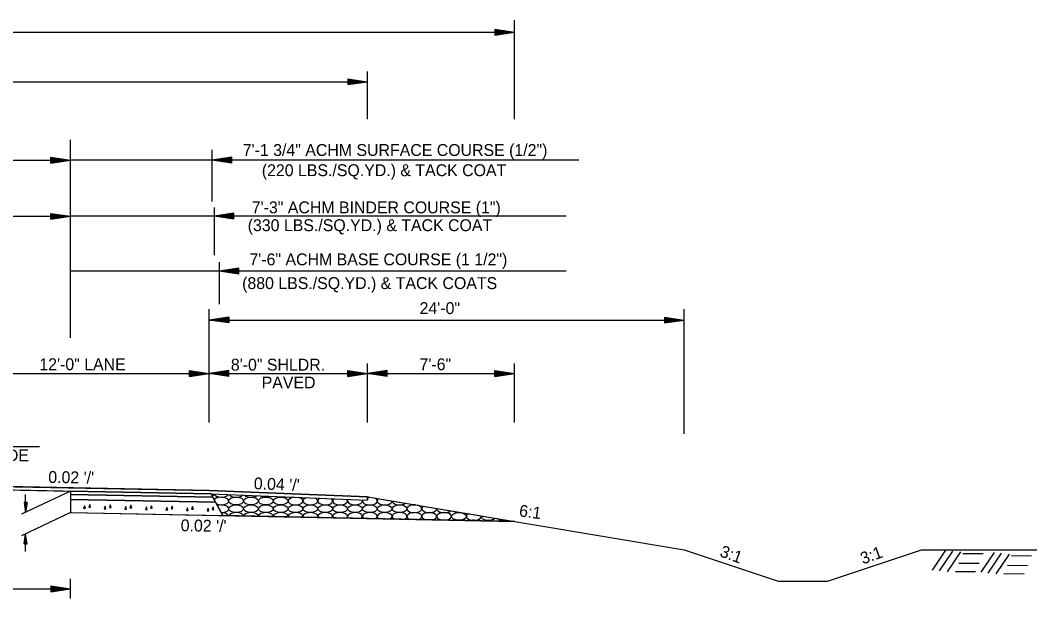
# Model space of a CAD drawing. Extents: x 1371763 to 1372860, y 385599 to 385872.
# Drawn here: x 1372091.9 to 1372143.2, y 385773 to 385802.2 of the extents above; entities that cross this region are included whole.
import ezdxf

# ---------------------------------------------------------------- set-up
doc = ezdxf.new("R2010")
doc.units = 0
doc.layers.add('R_Draft', color=7, linetype='Continuous')
doc.layers.add('R_Fin Surface', color=7, linetype='Continuous')

msp = doc.modelspace()

# ---------------------------------------------------------------- linework, layer by layer
at = {"layer": 'R_Draft'}
for p, q in [((1372115.827, 385801.752), (1372116.827, 385801.602)), ((1372115.827, 385801.752), (1372115.827, 385801.452)), ((1372116.827, 385797.204), (1372116.827, 385802.202)), ((1372049.964, 385801.602), (1372116.827, 385801.602)), ((1372115.827, 385801.727), (1372116.66, 385801.602)), ((1372115.827, 385801.701), (1372116.488, 385801.602)), ((1372115.827, 385801.676), (1372116.322, 385801.602)), ((1372115.827, 385801.65), (1372116.152, 385801.602)), ((1372115.827, 385801.625), (1372115.985, 385801.602)), ((1372115.827, 385801.452), (1372116.827, 385801.602)), ((1372115.827, 385801.553), (1372116.152, 385801.602)), ((1372115.827, 385801.502), (1372116.488, 385801.602)), ((1372115.827, 385801.477), (1372116.66, 385801.602)), ((1372115.827, 385801.527), (1372116.322, 385801.602)), ((1372115.827, 385801.578), (1372115.985, 385801.602)), ((1372108.395, 385799.252), (1372109.395, 385799.102)), ((1372108.395, 385799.252), (1372108.395, 385798.952)), ((1372108.395, 385799.227), (1372109.228, 385799.102)), ((1372108.395, 385799.201), (1372109.056, 385799.102)), ((1372109.395, 385797.204), (1372109.395, 385799.612)), ((1372057.395, 385799.102), (1372109.395, 385799.102)), ((1372108.395, 385799.176), (1372108.89, 385799.102)), ((1372108.395, 385799.15), (1372108.72, 385799.102)), ((1372108.395, 385799.125), (1372108.553, 385799.102)), ((1372108.395, 385798.952), (1372109.395, 385799.102)), ((1372108.395, 385799.053), (1372108.72, 385799.102)), ((1372108.395, 385799.002), (1372109.056, 385799.102)), ((1372108.395, 385798.977), (1372109.228, 385799.102)), ((1372108.395, 385799.027), (1372108.89, 385799.102)), ((1372108.395, 385799.078), (1372108.553, 385799.102)), ((1372094.394, 385786.159), (1372094.395, 385796.171)), ((1372101.532, 385795.66), (1372101.532, 385793.052)), ((1372072.395, 385795.139), (1372094.395, 385795.14)), ((1372093.395, 385795.29), (1372094.395, 385795.14)), ((1372093.395, 385794.99), (1372093.395, 385795.29)), ((1372093.395, 385795.265), (1372094.228, 385795.14)), ((1372093.395, 385795.239), (1372094.056, 385795.14)), ((1372093.395, 385795.214), (1372093.89, 385795.14)), ((1372093.395, 385795.189), (1372093.72, 385795.14)), ((1372093.395, 385795.163), (1372093.553, 385795.14)), ((1372093.395, 385794.99), (1372094.395, 385795.14)), ((1372093.395, 385795.091), (1372093.72, 385795.14)), ((1372093.395, 385795.04), (1372094.056, 385795.14)), ((1372093.395, 385795.015), (1372094.228, 385795.14)), ((1372093.395, 385795.065), (1372093.89, 385795.14)), ((1372093.395, 385795.116), (1372093.553, 385795.14)), ((1372120.071, 385795.139), (1372094.395, 385795.14)), ((1372102.532, 385795.29), (1372101.532, 385795.14)), ((1372102.532, 385794.99), (1372101.532, 385795.14)), ((1372102.532, 385795.265), (1372101.699, 385795.14)), ((1372102.532, 385795.015), (1372101.699, 385795.14)), ((1372102.532, 385795.239), (1372101.871, 385795.14)), ((1372102.532, 385795.04), (1372101.871, 385795.14)), ((1372102.532, 385795.214), (1372102.037, 385795.14)), ((1372102.532, 385795.065), (1372102.037, 385795.14)), ((1372102.532, 385795.189), (1372102.207, 385795.14)), ((1372102.532, 385795.091), (1372102.207, 385795.14)), ((1372102.532, 385795.163), (1372102.374, 385795.14)), ((1372102.532, 385795.116), (1372102.374, 385795.14)), ((1372102.532, 385794.99), (1372102.532, 385795.29)), ((1372101.647, 385792.752), (1372101.647, 385790.338)), ((1372072.395, 385792.301), (1372094.395, 385792.301)), ((1372093.395, 385792.451), (1372094.395, 385792.301)), ((1372093.395, 385792.151), (1372093.395, 385792.451)), ((1372093.395, 385792.426), (1372094.228, 385792.301)), ((1372093.395, 385792.401), (1372094.056, 385792.301)), ((1372093.395, 385792.376), (1372093.89, 385792.301)), ((1372093.395, 385792.35), (1372093.72, 385792.301)), ((1372093.395, 385792.325), (1372093.553, 385792.301)), ((1372093.395, 385792.151), (1372094.395, 385792.301)), ((1372093.395, 385792.253), (1372093.72, 385792.301)), ((1372093.395, 385792.202), (1372094.056, 385792.301)), ((1372093.395, 385792.176), (1372094.228, 385792.301)), ((1372093.395, 385792.227), (1372093.89, 385792.301)), ((1372093.395, 385792.278), (1372093.553, 385792.301)), ((1372119.437, 385792.302), (1372094.395, 385792.302)), ((1372102.647, 385792.452), (1372101.647, 385792.302)), ((1372102.647, 385792.152), (1372101.647, 385792.302)), ((1372102.647, 385792.427), (1372101.814, 385792.302)), ((1372102.647, 385792.177), (1372101.814, 385792.302)), ((1372102.647, 385792.401), (1372101.986, 385792.302)), ((1372102.647, 385792.202), (1372101.986, 385792.302)), ((1372102.647, 385792.376), (1372102.152, 385792.302)), ((1372102.647, 385792.227), (1372102.152, 385792.302)), ((1372102.647, 385792.351), (1372102.322, 385792.302)), ((1372102.647, 385792.253), (1372102.322, 385792.302)), ((1372102.647, 385792.325), (1372102.489, 385792.302)), ((1372102.647, 385792.278), (1372102.489, 385792.302)), ((1372102.647, 385792.152), (1372102.647, 385792.452)), ((1372101.896, 385789.977), (1372101.896, 385787.861)), ((1372119.437, 385789.527), (1372094.395, 385789.527)), ((1372102.896, 385789.677), (1372101.896, 385789.527)), ((1372102.896, 385789.377), (1372101.896, 385789.527)), ((1372102.896, 385789.652), (1372102.063, 385789.527)), ((1372102.896, 385789.402), (1372102.063, 385789.527)), ((1372102.896, 385789.626), (1372102.235, 385789.527)), ((1372102.896, 385789.427), (1372102.235, 385789.527)), ((1372102.896, 385789.601), (1372102.401, 385789.527)), ((1372102.896, 385789.452), (1372102.401, 385789.527)), ((1372102.896, 385789.576), (1372102.571, 385789.527)), ((1372102.896, 385789.478), (1372102.571, 385789.527)), ((1372102.896, 385789.55), (1372102.738, 385789.527)), ((1372102.896, 385789.503), (1372102.738, 385789.527)), ((1372102.896, 385789.377), (1372102.896, 385789.677)), ((1372101.392, 385781.89), (1372101.393, 385787.604)), ((1372125.393, 385781.306), (1372125.393, 385787.604)), ((1372102.393, 385787.213), (1372101.393, 385787.063)), ((1372101.393, 385787.063), (1372125.393, 385787.063)), ((1372102.393, 385786.913), (1372101.393, 385787.063)), ((1372102.393, 385787.188), (1372101.56, 385787.063)), ((1372102.393, 385786.938), (1372101.56, 385787.063)), ((1372102.393, 385787.163), (1372101.732, 385787.063)), ((1372102.393, 385786.964), (1372101.732, 385787.063)), ((1372102.393, 385787.138), (1372101.898, 385787.063)), ((1372102.393, 385786.989), (1372101.898, 385787.063)), ((1372102.393, 385787.112), (1372102.068, 385787.063)), ((1372102.393, 385787.014), (1372102.068, 385787.063)), ((1372102.393, 385787.087), (1372102.235, 385787.063)), ((1372102.393, 385787.04), (1372102.235, 385787.063)), ((1372102.393, 385787.213), (1372102.393, 385786.913)), ((1372124.393, 385787.213), (1372125.393, 385787.063)), ((1372124.393, 385787.213), (1372124.393, 385786.913)), ((1372124.393, 385787.188), (1372125.226, 385787.063)), ((1372124.393, 385787.163), (1372125.054, 385787.063)), ((1372124.393, 385787.138), (1372124.887, 385787.063)), ((1372124.393, 385787.112), (1372124.718, 385787.063)), ((1372124.393, 385787.087), (1372124.551, 385787.063)), ((1372124.393, 385786.913), (1372125.393, 385787.063)), ((1372124.393, 385787.014), (1372124.718, 385787.063)), ((1372124.393, 385786.964), (1372125.054, 385787.063)), ((1372124.393, 385786.938), (1372125.226, 385787.063)), ((1372124.393, 385786.989), (1372124.887, 385787.063)), ((1372124.393, 385787.04), (1372124.551, 385787.063)), ((1372109.392, 385781.885), (1372109.393, 385784.864)), ((1372116.827, 385781.885), (1372116.827, 385784.864)), ((1372089.393, 385784.357), (1372101.393, 385784.357)), ((1372100.393, 385784.507), (1372101.393, 385784.357)), ((1372100.393, 385784.207), (1372100.393, 385784.507)), ((1372100.393, 385784.482), (1372101.226, 385784.357)), ((1372100.393, 385784.456), (1372101.054, 385784.357)), ((1372100.393, 385784.431), (1372100.887, 385784.357)), ((1372100.393, 385784.406), (1372100.718, 385784.357)), ((1372100.393, 385784.38), (1372100.551, 385784.357)), ((1372100.393, 385784.207), (1372101.393, 385784.357)), ((1372100.393, 385784.308), (1372100.718, 385784.357)), ((1372100.393, 385784.257), (1372101.054, 385784.357)), ((1372100.393, 385784.232), (1372101.226, 385784.357)), ((1372100.393, 385784.282), (1372100.887, 385784.357)), ((1372100.393, 385784.333), (1372100.551, 385784.357)), ((1372102.393, 385784.506), (1372101.393, 385784.356)), ((1372102.393, 385784.206), (1372101.393, 385784.356)), ((1372101.393, 385784.356), (1372109.393, 385784.356)), ((1372102.393, 385784.481), (1372101.56, 385784.356)), ((1372102.393, 385784.231), (1372101.56, 385784.356)), ((1372102.393, 385784.455), (1372101.732, 385784.356)), ((1372102.393, 385784.256), (1372101.732, 385784.356)), ((1372102.393, 385784.43), (1372101.898, 385784.356)), ((1372102.393, 385784.281), (1372101.898, 385784.356)), ((1372102.393, 385784.405), (1372102.068, 385784.356)), ((1372102.393, 385784.307), (1372102.068, 385784.356)), ((1372102.393, 385784.379), (1372102.235, 385784.356)), ((1372102.393, 385784.332), (1372102.235, 385784.356)), ((1372102.393, 385784.206), (1372102.393, 385784.506)), ((1372108.393, 385784.506), (1372109.393, 385784.356)), ((1372108.393, 385784.206), (1372108.393, 385784.506)), ((1372108.393, 385784.481), (1372109.226, 385784.356)), ((1372108.393, 385784.455), (1372109.054, 385784.356)), ((1372108.393, 385784.43), (1372108.887, 385784.356)), ((1372108.393, 385784.405), (1372108.718, 385784.356)), ((1372108.393, 385784.379), (1372108.551, 385784.356)), ((1372108.393, 385784.206), (1372109.393, 385784.356)), ((1372108.393, 385784.307), (1372108.718, 385784.356)), ((1372108.393, 385784.256), (1372109.054, 385784.356)), ((1372108.393, 385784.231), (1372109.226, 385784.356)), ((1372108.393, 385784.281), (1372108.887, 385784.356)), ((1372108.393, 385784.332), (1372108.551, 385784.356)), ((1372110.393, 385784.506), (1372109.393, 385784.356)), ((1372110.393, 385784.206), (1372109.393, 385784.356)), ((1372109.393, 385784.356), (1372116.827, 385784.355)), ((1372110.393, 385784.481), (1372109.56, 385784.356)), ((1372110.393, 385784.231), (1372109.56, 385784.356)), ((1372110.393, 385784.455), (1372109.732, 385784.356)), ((1372110.393, 385784.256), (1372109.732, 385784.356)), ((1372110.393, 385784.43), (1372109.898, 385784.356)), ((1372110.393, 385784.281), (1372109.898, 385784.356)), ((1372110.393, 385784.405), (1372110.068, 385784.356)), ((1372110.393, 385784.307), (1372110.068, 385784.356)), ((1372110.393, 385784.379), (1372110.235, 385784.356)), ((1372110.393, 385784.332), (1372110.235, 385784.356)), ((1372110.393, 385784.206), (1372110.393, 385784.506)), ((1372115.827, 385784.505), (1372116.827, 385784.355)), ((1372115.827, 385784.205), (1372115.827, 385784.505)), ((1372115.827, 385784.48), (1372116.66, 385784.355)), ((1372115.827, 385784.455), (1372116.488, 385784.355)), ((1372115.827, 385784.43), (1372116.322, 385784.355)), ((1372115.827, 385784.404), (1372116.152, 385784.355)), ((1372115.827, 385784.379), (1372115.985, 385784.355)), ((1372115.827, 385784.205), (1372116.827, 385784.355)), ((1372115.827, 385784.307), (1372116.152, 385784.355)), ((1372115.827, 385784.256), (1372116.488, 385784.355)), ((1372115.827, 385784.23), (1372116.66, 385784.355)), ((1372115.827, 385784.281), (1372116.322, 385784.355)), ((1372115.827, 385784.332), (1372115.985, 385784.355)), ((1372085.645, 385780.681), (1372092.822, 385780.681)), ((1372083.395, 385778.806), (1372101.395, 385778.446)), ((1372083.395, 385778.639), (1372101.486, 385778.277)), ((1372094.395, 385778.419), (1372091.907, 385777.247)), ((1372092.12, 385777.347), (1372092.12, 385778.247)), ((1372101.395, 385778.446), (1372109.395, 385778.126)), ((1372101.486, 385778.277), (1372101.577, 385778.109)), ((1372101.486, 385778.277), (1372109.395, 385777.961)), ((1372092.045, 385777.847), (1372092.12, 385777.347)), ((1372092.195, 385777.847), (1372092.045, 385777.847)), ((1372092.057, 385777.847), (1372092.12, 385777.431)), ((1372092.07, 385777.847), (1372092.12, 385777.517)), ((1372092.082, 385777.847), (1372092.12, 385777.6)), ((1372092.095, 385777.847), (1372092.12, 385777.685)), ((1372092.108, 385777.847), (1372092.12, 385777.768)), ((1372092.195, 385777.847), (1372092.12, 385777.347)), ((1372092.144, 385777.847), (1372092.12, 385777.685)), ((1372092.169, 385777.847), (1372092.12, 385777.517)), ((1372092.182, 385777.847), (1372092.12, 385777.431)), ((1372092.157, 385777.847), (1372092.12, 385777.6)), ((1372092.131, 385777.847), (1372092.12, 385777.768)), ((1372094.395, 385778.002), (1372101.714, 385777.856)), ((1372101.577, 385778.109), (1372101.714, 385777.856)), ((1372101.714, 385777.856), (1372102.078, 385777.182)), ((1372109.395, 385778.126), (1372125.395, 385775.459)), ((1372109.395, 385778.126), (1372109.395, 385777.961)), ((1372094.395, 385777.335), (1372091.907, 385776.163)), ((1372094.395, 385777.336), (1372116.827, 385776.887)), ((1372092.045, 385775.763), (1372092.12, 385776.263)), ((1372092.057, 385775.763), (1372092.12, 385776.18)), ((1372092.07, 385775.763), (1372092.12, 385776.094)), ((1372092.195, 385775.763), (1372092.12, 385776.263)), ((1372092.12, 385775.363), (1372092.12, 385776.263)), ((1372092.182, 385775.763), (1372092.12, 385776.18)), ((1372092.169, 385775.763), (1372092.12, 385776.094)), ((1372092.045, 385775.763), (1372092.195, 385775.763)), ((1372092.082, 385775.763), (1372092.12, 385776.011)), ((1372092.095, 385775.763), (1372092.12, 385775.926)), ((1372092.108, 385775.763), (1372092.12, 385775.842)), ((1372092.157, 385775.763), (1372092.12, 385776.011)), ((1372092.144, 385775.763), (1372092.12, 385775.926)), ((1372092.131, 385775.763), (1372092.12, 385775.842)), ((1372137.936, 385774.428), (1372138.611, 385775.429)), ((1372138.294, 385774.386), (1372138.97, 385775.388)), ((1372138.695, 385774.344), (1372139.371, 385775.346)), ((1372139.471, 385775.271), (1372140.489, 385775.262)), ((1372140.388, 385774.319), (1372141.064, 385775.321)), ((1372140.747, 385774.278), (1372141.423, 385775.279)), ((1372141.148, 385774.236), (1372141.823, 385775.237)), ((1372141.923, 385775.162), (1372142.941, 385775.154)), ((1372139.27, 385774.787), (1372140.288, 385774.778)), ((1372141.723, 385774.678), (1372142.741, 385774.67)), ((1372139.095, 385774.361), (1372140.113, 385774.353)), ((1372141.548, 385774.253), (1372142.566, 385774.244)), ((1372093.395, 385773.637), (1372094.395, 385773.487)), ((1372093.395, 385773.637), (1372093.395, 385773.337)), ((1372093.395, 385773.612), (1372094.228, 385773.487)), ((1372093.395, 385773.586), (1372094.056, 385773.487)), ((1372093.395, 385773.561), (1372093.89, 385773.487)), ((1372093.395, 385773.535), (1372093.72, 385773.487)), ((1372093.395, 385773.51), (1372093.553, 385773.487)), ((1372094.395, 385772.987), (1372094.395, 385773.987)), ((1372072.395, 385773.487), (1372094.395, 385773.487)), ((1372093.395, 385773.337), (1372094.395, 385773.487)), ((1372093.395, 385773.438), (1372093.72, 385773.487)), ((1372093.395, 385773.387), (1372094.056, 385773.487)), ((1372093.395, 385773.362), (1372094.228, 385773.487)), ((1372093.395, 385773.412), (1372093.89, 385773.487)), ((1372093.395, 385773.463), (1372093.553, 385773.487))]:
    msp.add_line(p, q, dxfattribs=at)
for points in [[(1372083.395, 385778.806), (1372065.395, 385778.446), (1372057.395, 385778.126), (1372057.395, 385777.961), (1372065.305, 385778.277), (1372083.395, 385778.639), (1372094.395, 385778.419), (1372101.486, 385778.277), (1372109.395, 385777.961), (1372109.395, 385778.126), (1372101.395, 385778.446)], [(1372094.395, 385778.419), (1372094.395, 385778.252), (1372101.577, 385778.109), (1372101.486, 385778.277)], [(1372094.395, 385778.252), (1372094.395, 385778.002), (1372101.714, 385777.856), (1372101.577, 385778.109)], [(1372116.827, 385776.887), (1372102.078, 385777.182), (1372101.486, 385778.277), (1372109.395, 385777.961), (1372109.395, 385778.126), (1372110.697, 385777.909)], [(1372094.395, 385777.336), (1372102.078, 385777.182), (1372101.714, 385777.856), (1372094.395, 385778.002)]]:
    msp.add_lwpolyline(points, close=True, dxfattribs=at)
for points in [[(1372094.395, 385778.419), (1372094.395, 385778.252), (1372094.395, 385778.002), (1372094.395, 385777.336)], [(1372094.395, 385778.252), (1372101.577, 385778.109)], [(1372095.099, 385777.681), (1372095.051, 385777.548), (1372095.139, 385777.551), (1372095.099, 385777.681)], [(1372095.358, 385777.747), (1372095.31, 385777.614), (1372095.398, 385777.617), (1372095.358, 385777.747)], [(1372096.139, 385777.66), (1372096.091, 385777.527), (1372096.179, 385777.531), (1372096.139, 385777.66)], [(1372096.398, 385777.726), (1372096.35, 385777.593), (1372096.438, 385777.597), (1372096.398, 385777.726)], [(1372097.179, 385777.639), (1372097.131, 385777.506), (1372097.219, 385777.51), (1372097.179, 385777.639)], [(1372097.438, 385777.705), (1372097.39, 385777.572), (1372097.478, 385777.576), (1372097.438, 385777.705)], [(1372098.219, 385777.618), (1372098.17, 385777.485), (1372098.258, 385777.489), (1372098.219, 385777.618)], [(1372098.478, 385777.684), (1372098.429, 385777.551), (1372098.517, 385777.555), (1372098.478, 385777.684)], [(1372099.518, 385777.663), (1372099.469, 385777.531), (1372099.557, 385777.534), (1372099.518, 385777.663)], [(1372100.558, 385777.643), (1372100.509, 385777.51), (1372100.597, 385777.513), (1372100.558, 385777.643)], [(1372101.597, 385777.622), (1372101.549, 385777.489), (1372101.637, 385777.493), (1372101.597, 385777.622)], [(1372099.259, 385777.597), (1372099.21, 385777.465), (1372099.298, 385777.468), (1372099.259, 385777.597)], [(1372100.299, 385777.577), (1372100.25, 385777.444), (1372100.338, 385777.447), (1372100.299, 385777.577)], [(1372101.338, 385777.556), (1372101.29, 385777.423), (1372101.378, 385777.427), (1372101.338, 385777.556)]]:
    msp.add_lwpolyline(points, dxfattribs=at)
for centre, start_param, end_param in [((1372101.256, 385778.307), 5.569036, 6.099595), ((1372102.006, 385778.307), 3.327857, 5.942748), ((1372102.756, 385778.307), 3.491715, 5.778891), ((1372103.506, 385778.307), 3.669, 5.601604), ((1372104.257, 385778.307), 3.871715, 5.398888), ((1372105.007, 385778.307), 4.132787, 5.137813), ((1372102.006, 385777.918), 3.994914, 9.116844), ((1372102.006, 385777.53), 4.683046, 8.428712), ((1372105.757, 385777.918), 1.764076, 7.506516), ((1372106.507, 385777.918), 2.120937, 7.149665), ((1372107.258, 385777.918), 2.349472, 6.921132), ((1372108.008, 385777.918), 2.539026, 6.731578), ((1372108.758, 385777.918), 2.709482, 6.561124), ((1372109.509, 385777.918), 2.869677, 6.400928), ((1372109.509, 385778.307), 4.406366, 4.594074), ((1372109.509, 385777.918), 1.655955, 1.876819), ((1372109.509, 385777.918), 0.117743, 0.862934), ((1372110.259, 385777.918), 2.51534, 6.286734), ((1372111.009, 385777.918), 3.138048, 5.664025), ((1372111.759, 385777.53), 1.413362, 7.388711), ((1372111.759, 385777.918), 3.987393, 4.81468), ((1372112.51, 385777.53), 2.44532, 6.356754), ((1372102.006, 385777.141), 0.179125, 1.599901), ((1372102.756, 385777.141), 0.10068, 2.963715), ((1372103.506, 385777.141), 0.02309, 3.041305), ((1372104.257, 385777.141), 6.229056, 9.401709), ((1372105.007, 385777.141), 6.151745, 9.479021), ((1372105.757, 385777.141), 6.073871, 9.556894), ((1372106.507, 385777.141), 5.994935, 9.635831), ((1372107.258, 385777.141), 5.914372, 9.716393), ((1372108.008, 385777.141), 5.831514, 9.799251), ((1372108.758, 385777.141), 5.745523, 9.885243), ((1372109.509, 385777.141), 1.876819, 3.692298), ((1372109.509, 385777.141), 5.655282, 8.160004), ((1372110.259, 385777.141), 5.559213, 10.071552), ((1372111.009, 385777.141), 5.454888, 10.175877), ((1372111.759, 385777.141), 5.338136, 10.292629), ((1372112.51, 385777.141), 5.200434, 10.430331), ((1372113.26, 385777.141), 5.017004, 10.613761), ((1372113.26, 385777.53), 3.06973, 5.732344), ((1372114.01, 385777.53), 3.846034, 4.95604), ((1372114.76, 385777.141), 2.37325, 6.428824), ((1372115.511, 385777.141), 3.002534, 5.799539), ((1372114.01, 385776.753), 1.330127, 1.734267), ((1372114.76, 385776.753), 1.08688, 1.977514), ((1372115.511, 385776.753), 0.932125, 2.132269), ((1372116.261, 385777.141), 3.731542, 5.070532), ((1372116.261, 385776.753), 0.806619, 2.257775), ((1372117.011, 385776.753), 2.298525, 2.367522)]:
    msp.add_ellipse(centre, major_axis=(0.375, 0), ratio=0.517889, start_param=start_param, end_param=end_param, dxfattribs=at)
for centre in [(1372102.756, 385777.918), (1372102.756, 385777.53), (1372103.506, 385777.918), (1372103.506, 385777.53), (1372104.257, 385777.918), (1372104.257, 385777.53), (1372105.007, 385777.918), (1372105.007, 385777.53), (1372105.757, 385777.53), (1372106.507, 385777.53), (1372107.258, 385777.53), (1372108.008, 385777.53), (1372108.758, 385777.53), (1372109.509, 385777.53), (1372110.259, 385777.53), (1372111.009, 385777.53), (1372114.01, 385777.141)]:
    msp.add_ellipse(centre, major_axis=(0.375, 0), ratio=0.517889, dxfattribs=at)
at = {"layer": 'R_Fin Surface'}
for p, q in [((1372125.395, 385775.459), (1372130.139, 385773.878)), ((1372132.639, 385773.878), (1372137.382, 385775.459)), ((1372137.382, 385775.459), (1372143.2, 385775.459)), ((1372130.139, 385773.878), (1372132.639, 385773.878))]:
    msp.add_line(p, q, dxfattribs=at)

# ---------------------------------------------------------------- texts
at = {"layer": 'R_Draft'}
for s, rotation, p in [('7\'-1 3/4" ACHM SURFACE COURSE (1/2")', 0, (1372103.091, 385795.35)), ('(220 LBS./SQ.YD.) & TACK COAT', 0, (1372104.053, 385794.33)), ('7\'-3" ACHM BINDER COURSE (1")', 0, (1372103.546, 385792.452)), ('(330 LBS./SQ.YD.) & TACK COAT', 0, (1372103.341, 385791.552)), ('7\'-6" ACHM BASE COURSE (1 1/2")', 360, (1372103.428, 385789.827)), ('(880 LBS./SQ.YD.) & TACK COATS', 360, (1372103.059, 385788.627)), ('12\'-0" LANE', 360, (1372092.814, 385784.528)), ('8\'-0" SHLDR.', 360, (1372102.489, 385784.506)), ('7\'-6"', 360, (1372112.021, 385784.527)), ('PAVED', 360, (1372104.046, 385783.606)), ("0.02 '/'", 359.0147, (1372093.261, 385778.838)), ("0.04 '/'", 357.6223, (1372103.64, 385778.518)), ('6:1', 352.2846, (1372117.025, 385777.15)), ("0.02 '/'", 359.0147, (1372099.952, 385776.395)), ('3:1', 340.0022, (1372127.149, 385775.137)), ('3:1', 19.9978, (1372134.422, 385774.711))]:
    msp.add_text(s, height=0.6, rotation=rotation, dxfattribs=at).set_placement(p)
for s, p in [('24\'-0"', (1372112.025, 385787.363)), ('PROFILE GRADE', (1372085.779, 385779.931))]:
    msp.add_text(s, height=0.6, dxfattribs=at).set_placement(p)

doc.saveas('drawing.dxf')
